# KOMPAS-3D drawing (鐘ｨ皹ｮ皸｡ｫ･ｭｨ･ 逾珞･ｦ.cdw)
File: created 11.12.2016 22:15:24, last saved 24.12.2016 15:35:27.
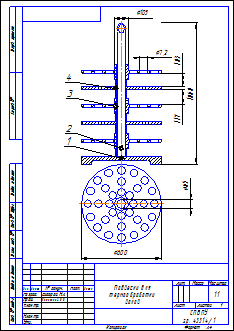
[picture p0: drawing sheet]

Sheet 1: A4, portrait

Title block, sheet 1: name: Подвески для / термообработки / валов; scale: 1:1; sheets: 1; organisation: СПБПУ / гр. 43314/1; sheet format: A4; stored path: C:\Users\nikit\OneDrive\Документы\Лабораторные\4 курс\Курсовая печи\Приспособление чертеж.cdw; drawn by: Сидоров Н.А.; checked by: Кисленков В.В.

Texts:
  Никита
Dimensions and other numbers on the sheet: 600; 1060; 7,2; 105; 65; 103; 117; 1; 2; 3; 4; 1:1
